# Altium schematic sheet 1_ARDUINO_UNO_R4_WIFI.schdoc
size 601 x 429 mm; Symbol: Drawing-Symbol_A4; Device: Drawing-Symbol_A4; @Project Name: Slowpoke; @Page Count: 1; @Update Date: 2025-12-13; @Create Date: 2025-12-13; @Schematic Name: Schematic2; @Page No: 1; @Page Name: ARDUINO_UNO_R4_WIFI; Company: EasyEDA.com; Version: V1.0; Page Size: A4; @Create Time: 06:28:29; @Update Time: 14:28:55; Width: 2338; Height: 1652; Region Start: 1; X Region Count: 6; Y Region Count: 4; Blade Width: 10; Title Block Position: 3; @Board Name: ARDUINO
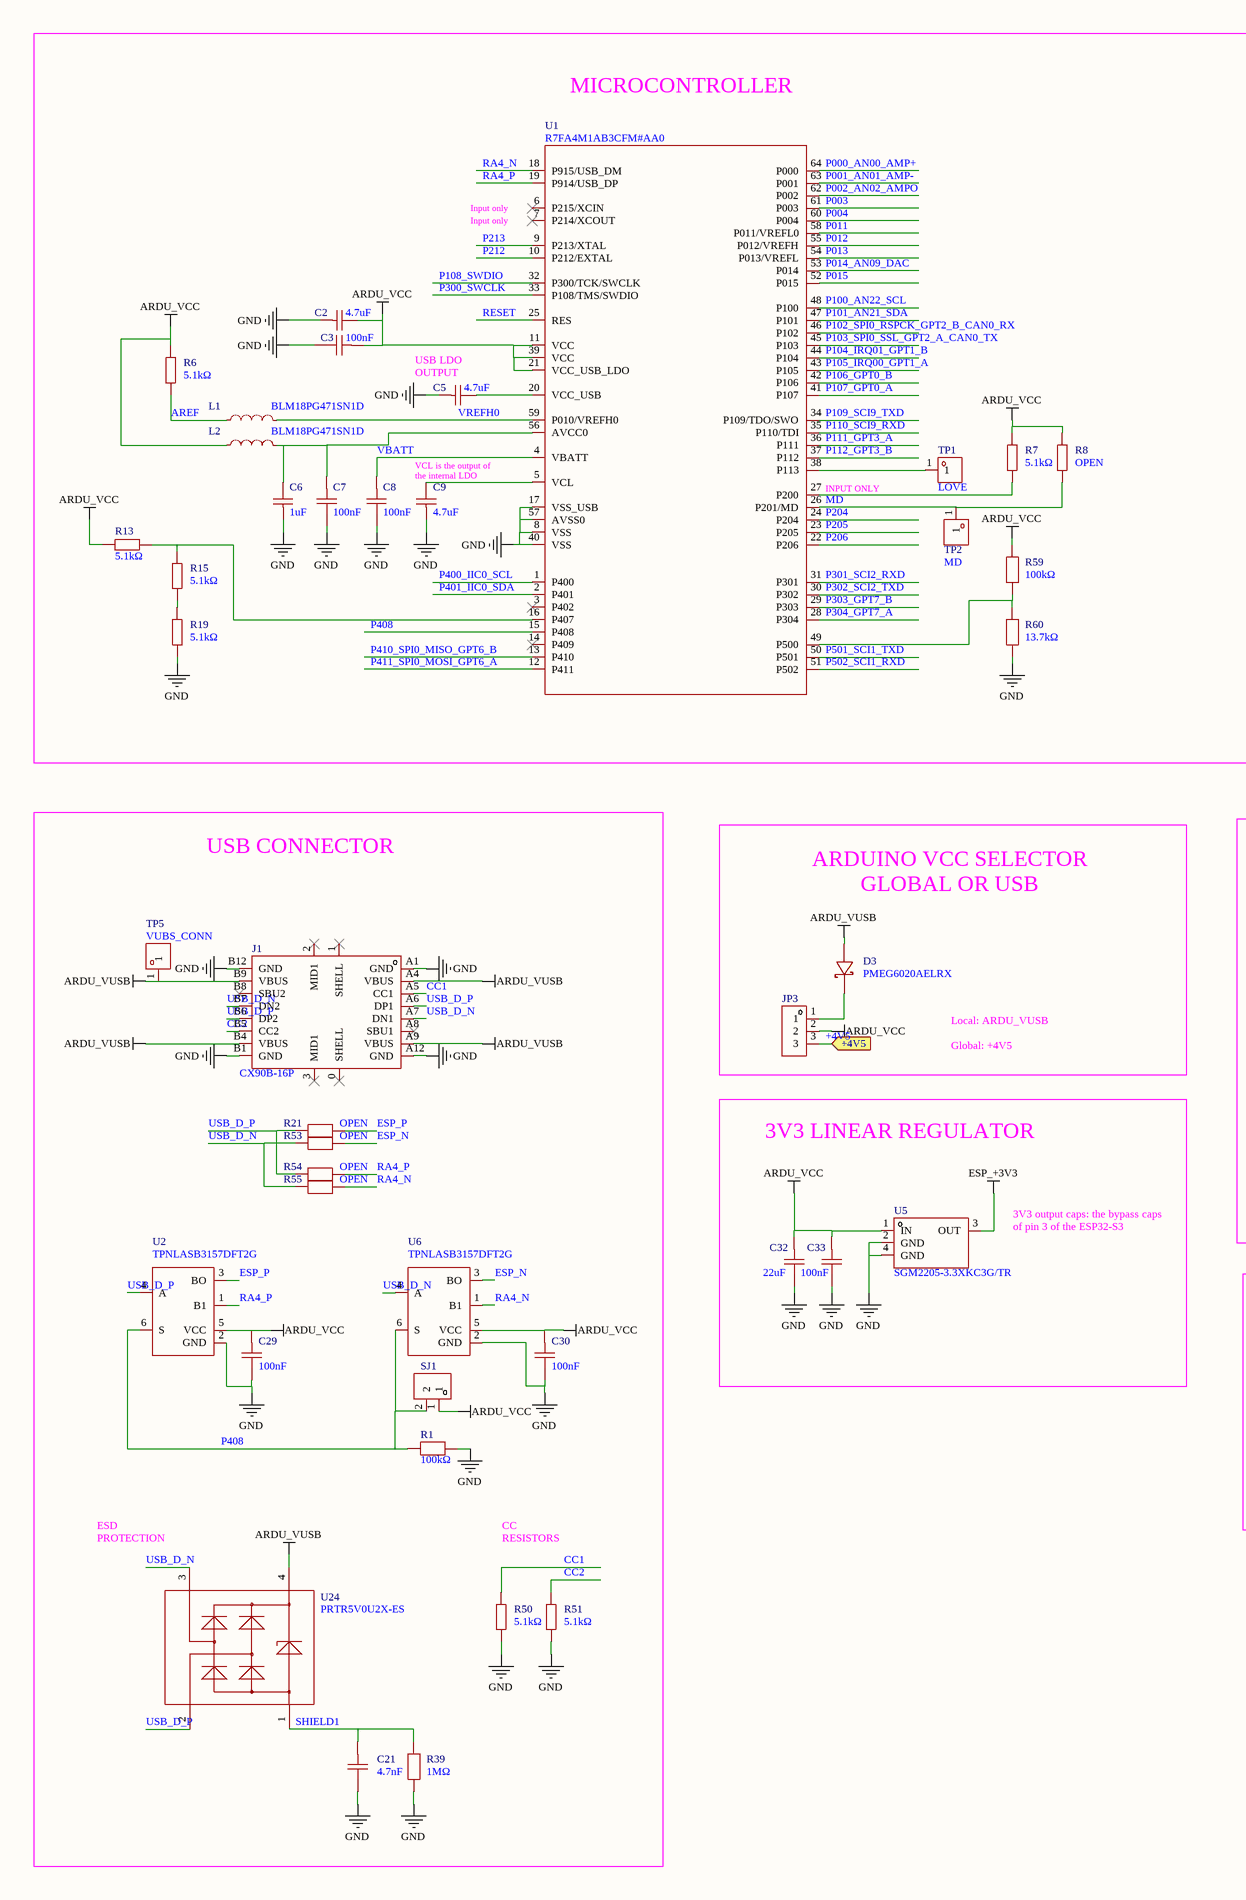
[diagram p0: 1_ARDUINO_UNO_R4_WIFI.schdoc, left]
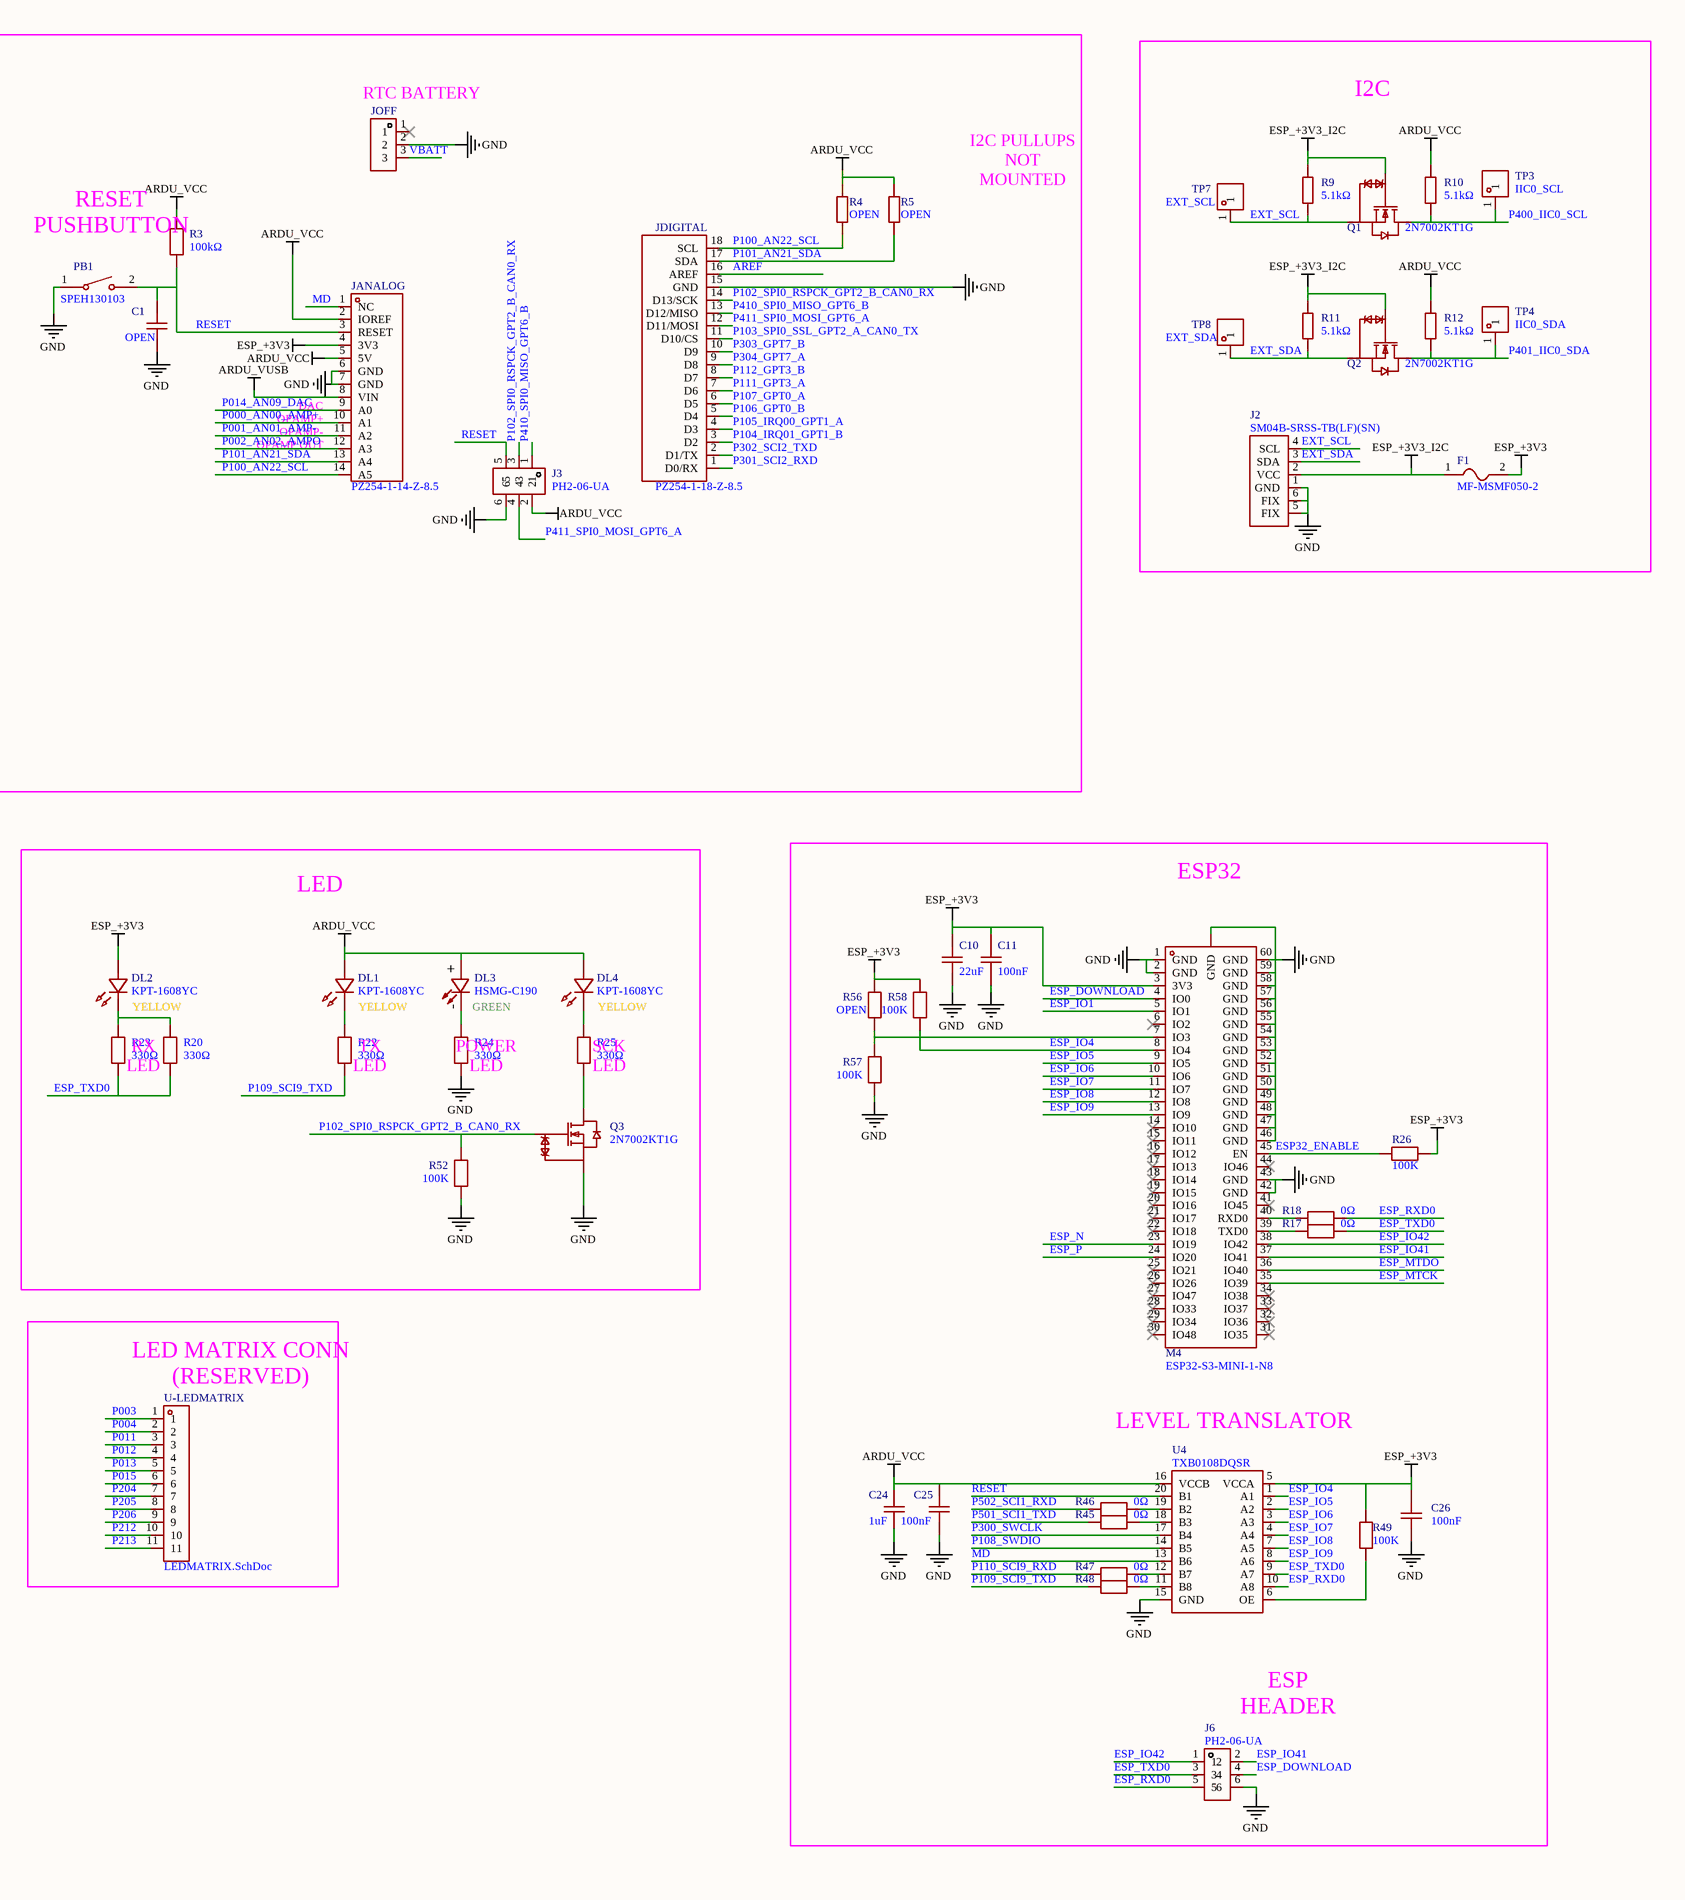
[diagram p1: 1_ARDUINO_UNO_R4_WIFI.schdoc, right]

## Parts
C1  OPEN  [C0402]
C2  4.7uF  [C0402]
C3  100nF  [C0402]
C5  4.7uF  [C0402]
C6  1uF  [C0402]
C7  100nF  [C0402]
C8  100nF  [C0402]
C9  4.7uF  [C0402]
C10  22uF  [C0805]
C11  100nF  [C0402]
C21  4.7nF  [C0805]
C24  1uF  [C0402]
C25  100nF  [C0402]
C26  100nF  [C0402]
C29  100nF  [C0402]
C30  100nF  [C0402]
C32  22uF  [C0805]
C33  100nF  [C0402]
D3  PMEG6020AELRX  [SOD-123_L2.6-W1.7-LS3.5-RD]
DL1  KPT-1608YC  [LED-SMD_L1.6-W0.8-RD]
DL2  KPT-1608YC  [LED-SMD_L1.6-W0.8-RD]
DL3  HSMG-C190  [LED-SMD_L1.6-W0.8-R-RD]
DL4  KPT-1608YC  [LED-SMD_L1.6-W0.8-RD]
F1  MF-MSMF050-2  [F1812]
J1  CX90B-16P  [USB-C-SMD_CX90B-16P]
J2  SM04B-SRSS-TB(LF)(SN)  [CONN-SMD_4P-P1.00_SM04B-SRSS-TB-LF-SN]
J3  PH2-06-UA  [HDR-TH_6P-P2.54-V-M-R2-C3-S2.54-1]
J6  PH2-06-UA  [HDR-TH_6P-P2.54-V-M-R2-C3-S2.54-1]
JANALOG  PZ254-1-14-Z-8.5  [HDR-TH_14P-P2.54-V-M]
JDIGITAL  PZ254-1-18-Z-8.5  [HDR-TH_18P-P2.54-V-M]
JOFF  PZ254V-11-03P  [HDR-TH_3P-P2.54-V-M]  (value not drawn)
JP3  PZ254V-11-03P  [HDR-TH_3P-P2.54-V-M]  (value not drawn)
L1  BLM18PG471SN1D  [L0603]
L2  BLM18PG471SN1D  [L0603]
M4  ESP32-S3-MINI-1-N8  [BULETM-SMD_ESP32-S3-MINI-1-N8]
PB1  SPEH130103  [SW-SMD_L6.0-W6.0-LS6.6]
Q1  2N7002KT1G  [SOT-23-3_L2.9-W1.3-P1.90-LS2.4-BR]
Q2  2N7002KT1G  [SOT-23-3_L2.9-W1.3-P1.90-LS2.4-BR]
Q3  2N7002KT1G  [SOT-23-3_L2.9-W1.3-P1.90-LS2.4-BR]
R1  100kΩ  [R0402]
R3  100kΩ  [R0402]
R4  OPEN  [R0402]
R5  OPEN  [R0402]
R6  5.1kΩ  [R0402]
R7  5.1kΩ  [R0402]
R8  OPEN  [R0402]
R9  5.1kΩ  [R0402]
R10  5.1kΩ  [R0402]
R11  5.1kΩ  [R0402]
R12  5.1kΩ  [R0402]
R13  5.1kΩ  [R0402]
R15  5.1kΩ  [R0402]
R17  0Ω  [R0402]
R18  0Ω  [R0402]
R19  5.1kΩ  [R0402]
R20  330Ω  [R0402]
R21  OPEN  [R0402]
R22  330Ω  [R0402]
R23  330Ω  [R0402]
R24  330Ω  [R0402]
R25  330Ω  [R0402]
R26  100K  [R0402]
R39  1MΩ  [R0402]
R45  0Ω  [R0402]
R46  0Ω  [R0402]
R47  0Ω  [R0402]
R48  0Ω  [R0402]
R49  100K  [R0402]
R50  5.1kΩ  [R0402]
R51  5.1kΩ  [R0402]
R52  100K  [R0402]
R53  OPEN  [R0402]
R54  OPEN  [R0402]
R55  OPEN  [R0402]
R56  OPEN  [R0402]
R57  100K  [R0402]
R58  100K  [R0402]
R59  100kΩ  [R0402]
R60  13.7kΩ  [R0402]
SJ1  IOVDD_1797  [HDR-TH_2P-P2.54-V-M]  (value not drawn)
TP1  LOVE  [TESTPOINT-TH_BD3.2]
TP2  MD  [TESTPOINT-TH_BD3.2]
TP3  IIC0_SCL  [TESTPOINT-TH_BD3.2]
TP4  IIC0_SDA  [TESTPOINT-TH_BD3.2]
TP5  VUBS_CONN  [TESTPOINT-TH_BD3.2]
TP7  EXT_SCL  [TESTPOINT-TH_BD3.2]
TP8  EXT_SDA  [TESTPOINT-TH_BD3.2]
U1  R7FA4M1AB3CFM#AA0  [LQFP-64_L10.0-W10.0-P0.50-LS12.0-BL]
U2  TPNLASB3157DFT2G  [SOT-363-6_L2.0-W1.3-P0.65-LS2.3-BL]
U4  TXB0108DQSR  [SON-20_L4.0-W2.0-P0.40-BL]
U5  SGM2205-3.3XKC3G/TR  [SOT-223-3_L6.5-W3.4-P2.30-LS7.0-BR]
U6  TPNLASB3157DFT2G  [SOT-363-6_L2.0-W1.3-P0.65-LS2.3-BL]
U24  PRTR5V0U2X-ES  [SOT-143_L2.9-W1.3-P1.92-LS2.3-BR]
U-LEDMATRIX  LEDMATRIX.SchDoc  [HDR-TH_11P-P2.54-V-M]

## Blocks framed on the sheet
MICROCONTROLLER: C1-C3 C5-C9 J3 JANALOG JDIGITAL JOFF L1 L2 PB1 R3-R8 R13 R15 R19 R59 R60 TP1 TP2 U1
I2C: F1 J2 Q1 Q2 R9-R12 TP3 TP4 TP7 TP8
USB CONNECTOR: C21 C29 C30 J1 R1 R21 R39 R50 R51 R53-R55 SJ1 TP5 U2 U6 U24
LED: DL1-DL4 Q3 R20 R22-R25 R52
3V3 LINEAR REGULATOR: C32 C33 U5

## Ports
+4V5 (in)

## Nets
ARDU_VCC: C2.2 C3.2 C24.2 C25.2 C29.2 C30.2 C32.2 C33.2 DL1.2(A) DL3.1(A) DL4.2(A) J3.2 JANALOG.2(IOREF) JANALOG.5(5V) JP3.2 L2.1 R3.2 R4.2 R5.2 R6.2 R7.2 R8.2 R10.2 R12.2 R13.2 R59.2 SJ1.1 U1.11(VCC) U1.21(VCC_USB_LDO) U1.39(VCC) U2.5(VCC) U4.16(VCCB) U5.1(IN) U6.5(VCC)
ARDU_VUSB: D3.2(+) J1.A4(VBUS) J1.A9(VBUS) J1.B4(VBUS) J1.B9(VBUS) JANALOG.8(VIN) TP5.1 U24.4(VCC)
ESP_+3V3: C10.2 C11.2 C26.2 DL2.2(A) F1.2 JANALOG.4(3V3) M4.3(3V3) R26.1 R49.2 R56.2 R58.2 U4.5(VCCA) U5.3(OUT)
ESP_+3V3_I2C: F1.1 J2.2(VCC) Q1.1(G) Q2.1(G) R9.2 R11.2
GND: C1.1 C2.1 C3.1 C5.1 C6.1 C7.1 C8.1 C9.1 C10.1 C11.1 C21.1 C24.1 C25.1 C26.1 C29.1 C30.1 C32.1 C33.1 J1.A1(GND) J1.A12(GND) J1.B1(GND) J1.B12(GND) J2.1(GND) J2.5(FIX) J2.6(FIX) J3.6 J6.6 JANALOG.6(GND) JANALOG.7(GND) JDIGITAL.15(GND) JOFF.2 M4.1(GND) M4.2(GND) M4.42(GND) M4.43(GND) M4.46(GND) M4.47(GND) M4.48(GND) M4.49(GND) M4.50(GND) M4.51(GND) M4.52(GND) M4.53(GND) M4.54(GND) M4.55(GND) M4.56(GND) M4.57(GND) M4.58(GND) M4.59(GND) M4.60(GND) M4.GND PB1.1 Q3.2(S) R1.1 R19.1 R24.1 R39.1 R50.1 R51.1 R52.1 R57.1 R60.1 U1.8(VSS) U1.17(VSS_USB) U1.40(VSS) U1.57(AVSS0) U2.2(GND) U4.15(GND) U5.2(GND) U5.4(GND) U6.2(GND)
+4V5: JP3.3 ; port +4V5
AREF: JDIGITAL.16(AREF) L1.1 R6.1
CC1: J1.A5(CC1) R50.2
CC2: J1.B5(CC2) R51.2
ESP32_ENABLE: M4.45(EN) R26.2
ESP_DOWNLOAD: J6.4 M4.4(IO0)
ESP_IO1: M4.5(IO1)
ESP_IO4: M4.8(IO4) R58.1 U4.1(A1)
ESP_IO5: M4.9(IO5) U4.2(A2)
ESP_IO6: M4.10(IO6) U4.3(A3)
ESP_IO7: M4.11(IO7) U4.4(A4)
ESP_IO8: M4.12(IO8) U4.7(A5)
ESP_IO9: M4.13(IO9) U4.8(A6)
ESP_IO41: J6.2 M4.37(IO41)
ESP_IO42: J6.1 M4.38(IO42)
ESP_MTCK: M4.35(IO39)
ESP_MTDO: M4.36(IO40)
ESP_N: M4.23(IO19) R53.2 U6.3(BO)
ESP_P: M4.24(IO20) R21.2 U2.3(BO)
ESP_RXD0: J6.5 R18.2 U4.10(A8)
ESP_TXD0: J6.3 R17.2 R20.1 R23.1 U4.9(A7)
EXT_SCL: J2.4(SCL) Q1.2(S) R9.1 TP7.1
EXT_SDA: J2.3(SDA) Q2.2(S) R11.1 TP8.1
MD: JANALOG.1(NC) R8.1 TP2.1 U1.26(P201/MD) U4.13(B6)
P000_AN00_AMP+: JANALOG.10(A1) U1.64(P000)
P001_AN01_AMP-: JANALOG.11(A2) U1.63(P001)
P002_AN02_AMPO: JANALOG.12(A3) U1.62(P002)
P003: U1.61(P003) U-LEDMATRIX.1
P004: U1.60(P004) U-LEDMATRIX.2
P011: U1.58(P011/VREFL0) U-LEDMATRIX.3
P012: U1.55(P012/VREFH) U-LEDMATRIX.4
P013: U1.54(P013/VREFL) U-LEDMATRIX.5
P014_AN09_DAC: JANALOG.9(A0) U1.53(P014)
P015: U1.52(P015) U-LEDMATRIX.6
P100_AN22_SCL: JANALOG.14(A5) JDIGITAL.18(SCL) R4.1 U1.48(P100)
P101_AN21_SDA: JANALOG.13(A4) JDIGITAL.17(SDA) R5.1 U1.47(P101)
P102_SPI0_RSPCK_GPT2_B_CAN0_RX: J3.3 JDIGITAL.14(D13/SCK) Q3.1(G) R52.2 U1.46(P102)
P103_SPI0_SSL_GPT2_A_CAN0_TX: JDIGITAL.11(D10/CS) U1.45(P103)
P104_IRQ01_GPT1_B: JDIGITAL.3(D2) U1.44(P104)
P105_IRQ00_GPT1_A: JDIGITAL.4(D3) U1.43(P105)
P106_GPT0_B: JDIGITAL.5(D4) U1.42(P106)
P107_GPT0_A: JDIGITAL.6(D5) U1.41(P107)
P108_SWDIO: U1.32(P300/TCK/SWCLK) U4.14(B5)
P109_SCI9_TXD: R22.1 R48.1 U1.34(P109/TDO/SWO)
P110_SCI9_RXD: R47.1 U1.35(P110/TDI)
P111_GPT3_A: JDIGITAL.7(D6) U1.36(P111)
P112_GPT3_B: JDIGITAL.8(D7) U1.37(P112)
P204: U1.24(P204) U-LEDMATRIX.7
P205: U1.23(P205) U-LEDMATRIX.8
P206: U1.22(P206) U-LEDMATRIX.9
P212: U1.10(P212/EXTAL) U-LEDMATRIX.10
P213: U1.9(P213/XTAL) U-LEDMATRIX.11
P300_SWCLK: U1.33(P108/TMS/SWDIO) U4.17(B4)
P301_SCI2_RXD: JDIGITAL.1(D0/RX) U1.31(P301)
P302_SCI2_TXD: JDIGITAL.2(D1/TX) U1.30(P302)
P303_GPT7_B: JDIGITAL.10(D9) U1.29(P303)
P304_GPT7_A: JDIGITAL.9(D8) U1.28(P304)
P400_IIC0_SCL: Q1.3(D) R10.1 TP3.1 U1.1(P400)
P401_IIC0_SDA: Q2.3(D) R12.1 TP4.1 U1.2(P401)
P408: R1.2 SJ1.2 U1.15(P408) U2.6(S) U6.6(S)
P410_SPI0_MISO_GPT6_B: J3.1 JDIGITAL.13(D12/MISO) U1.13(P410)
P411_SPI0_MOSI_GPT6_A: J3.4 JDIGITAL.12(D11/MOSI) U1.12(P411)
P501_SCI1_TXD: R45.1 U1.50(P501)
P502_SCI1_RXD: R46.1 U1.51(P502)
RA4_N: R55.2 U1.18(P915/USB_DM) U6.1(B1)
RA4_P: R54.2 U1.19(P914/USB_DP) U2.1(B1)
RESET: C1.2 J3.5 JANALOG.3(RESET) PB1.2 R3.1 U1.25(RES) U4.20(B1)
SHIELD1: C21.2 R39.2 U24.1(GND)
USB_D_N: J1.A7(DN1) J1.B7(DN2) R53.1 R55.1 U6.4(A) U24.3(IO)
USB_D_P: J1.A6(DP1) J1.B6(DP2) R21.1 R54.1 U2.4(A) U24.2(IO)
VBATT: C8.2 JOFF.3 U1.4(VBATT)
VREFH0: L1.2 U1.59(P010/VREFH0)
NetC5_2: C5.2 U1.20(VCC_USB)
NetC6_2: C6.2 C7.2 L2.2 U1.56(AVCC0)
NetC9_2: C9.2 U1.5(VCL)
NetD3_1: D3.1(-) JP3.1
NetDL1_1: DL1.1(K) R22.2
NetDL2_1: DL2.1(K) R20.2 R23.2
NetDL3_2: DL3.2(C) R24.2
NetDL4_1: DL4.1(K) R25.2
NetM4_7: M4.7(IO3) R56.1 R57.2
NetM4_39: M4.39(TXD0) R17.1
NetM4_40: M4.40(RXD0) R18.1
NetQ3_3: Q3.3(D) R25.1
NetR7_1: R7.1 U1.27(P200)
NetR13_1: R13.1 R15.2 U1.16(P407)
NetR15_1: R15.1 R19.2
NetR45_2: R45.2 U4.18(B3)
NetR46_2: R46.2 U4.19(B2)
NetR47_2: R47.2 U4.12(B7)
NetR48_2: R48.2 U4.11(B8)
NetR49_1: R49.1 U4.6(OE)
NetR59_1: R59.1 R60.2 U1.49(P500)
NetTP1_1: TP1.1 U1.38(P113)

Not connected (* = marked no-connect by the designer): J1 0(SHELL)* 1(SHELL)* 2(MID1)* 3(MID1)* A8(SBU1)* B8(SBU2)*; JOFF 1*; M4 6(IO2)* 14(IO10)* 15(IO11)* 16(IO12)* 17(IO13)* 18(IO14)* 19(IO15)* 20(IO16)* 21(IO17)* 22(IO18)* 25(IO21)* 26(IO26)* 27(IO47)* 28(IO33)* 29(IO34)* 30(IO48)* 31(IO35)* 32(IO36)* 33(IO37)* 34(IO38)* 41(IO45)* 44(IO46)*; U1 3(P402)* 6(P215/XCIN)* 7(P214/XCOUT)* 14(P409)*

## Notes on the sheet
- (near JOFF) RTC BATTERY
- RESET
  PUSHBUTTON
- I2C PULLUPS
  NOT
  MOUNTED
- (near U1) Input only
- (near C5) USB LDO
  OUTPUT
- (near JANALOG) DAC
  OPAMP+
  OPAMP-
  OPAMP OUT
- (near C9) VCL is the output of
  the internal LDO
- (near U1) INPUT ONLY
- (near D3) ARDUINO VCC SELECTOR
  GLOBAL OR USB
- ESP32
- YELLOW
- GREEN
- Local: ARDU_VUSB
  Global: +4V5
- RX
  LED
- (near R22) TX
  LED
- POWER
  LED
- SCK
  LED
- (near U5) 3V3 output caps: the bypass caps
  of pin 3 of the ESP32-S3
- (near U-LEDMATRIX) LED MATRIX CONN
  (RESERVED)
- LEVEL TRANSLATOR
- (near U24) ESD
  PROTECTION
- CC
  RESISTORS
- (near J6) ESP
  HEADER

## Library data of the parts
C1 = CC0402KRX7R6BB474: Manufacturer: YAGEO(国巨); Add into BOM: yes; Tolerance: ±10%; Voltage Rating: 10V; Temperature Coefficient: X7R
C2 C5 C6 C9 C24 = CL05A105KP5NNNC: Manufacturer: SAMSUNG(三星); Add into BOM: yes; Tolerance: ±10%; Voltage Rating: 10V; Temperature Coefficient: X5R
C3 C7 C8 C11 C25 C26 C29 C30 C33 = GRM155R61H104KE19D: Manufacturer: muRata(村田); Add into BOM: yes; Tolerance: ±10%
C10 C32 = CL21A226MAQNNNE: Manufacturer: SAMSUNG(三星); Add into BOM: yes; Tolerance: ±20%; Voltage Rating: 25V; Temperature Coefficient: X5R
C21 = FV21X472K102ECG: Manufacturer: PSA(信昌电陶); Add into BOM: yes; Tolerance: ±10%; Voltage Rating: 1kV; Temperature Coefficient: X7R
D3 = PMEG6020AELRX: Manufacturer: Nexperia(安世); Add into BOM: yes; Forward Voltage (Vf@If): 670mV@2A; Reverse Voltage (Vr): 60V; Average Rectified Current (Io): 2A; Reverse Leakage Current (Ir): 700nA@60V
DL1 DL2 DL4 = VFHL1116P-4BX3C-TR: Manufacturer: Stanley Electric; Add into BOM: yes; Illumination Color: Emerald; Voltage - Forward(Vf): 1.9V; Forward Current: 20mA; Wavelength - Dominant: 562nm; Peak Wavelength: 565nm; Lens Color: White Lens; Luminous Intensity: 82mcd
DL3 = HSMG-C190: Manufacturer: Broadcom(博通); Add into BOM: yes; Illumination Color: Green; Voltage - Forward(Vf): 2.2V; Power(Watts): 52mW; Forward Current: 20mA; Wavelength - Dominant: 572nm; Peak Wavelength: 570nm; Luminous Intensity: 15mcd; Viewing Angle: 170°
F1 = MF-MSMF050-2: Manufacturer: BOURNS; Add into BOM: yes; Voltage - Max: 15V; Current - Max: 100A; Hold Current: 500mA; Trip Current: 1A; Resistance - Initial (Ri) (Min): 150mΩ; Resistance - Post Trip (R1) (Max): 1Ω; Time to Trip(Max): 150ms
J1 = CX90B-16P: Manufacturer: HRS(广濑); Add into BOM: yes
J2 = SM04B-SRSS-TB(LF)(SN): Manufacturer: JST; Add into BOM: yes; Pins Structure: 1x4P; Pitch: 1mm; Reference Series: SH; Number of PINs Per Row: 4; Current Rating: 1A; Voltage Rating: 50V; Plastic Material: PA; Flame Retardant Rating: UL94V-0; Supplementary Features: Auxiliary Solder Pin; Z-Height of the Board: 2.9mm; X-Length of Bottom Edge on Board (Spacing Line): 6mm; Y-Width of Bottom Edge on Board: 4.32mm
J3 J6 = PH2-06-UA: Manufacturer: ADAM TECH; Add into BOM: yes; Pitch: 2.54mm; Circluar Pins/Square Pins: Pin Header; Current Rating: 3A; Voltage Rating (Max): 250V
JANALOG = PZ254-1-14-Z-8.5: Manufacturer: HCTL(华灿天禄); Symbol: PM254-1-14-Z-8.5; Add into BOM: yes; Pin Structure: 1x14P; Pitch: 2.54mm; Circluar Pins/Square Pins: Policy; Current Rating: 3A
JDIGITAL = PZ254-1-18-Z-8.5: Manufacturer: HCTL(华灿天禄); Symbol: PM254-1-18-Z-8.5; Add into BOM: yes; Pin Structure: 1x18P; Pitch: 2.54mm; Circluar Pins/Square Pins: Pin Header; Current Rating: 3A
JOFF JP3 = PZ254V-11-03P: Manufacturer: XFCN(兴飞); Symbol: PZ254V-11-03P_C2937625; Add into BOM: yes; Pin Structure: 1x3P; Pitch: 2.54mm; Circluar Pins/Square Pins: Pin Header; Current Rating: 3A; Voltage Rating (Max): 250V
L1 L2 = BLM18PG471SN1D: Manufacturer: muRata(村田); Add into BOM: yes; Impedance @ Frequency: 470Ω@100MHz; Tolerance: ±25%; DC Resistance(DCR): 200mΩ; Current Rating: 1A; Number of Circuits: 1
M4 = ESP32-S3-MINI-1-N8: Manufacturer: ESPRESSIF(乐鑫); Add into BOM: yes; Core Processor: ESP32-S3FN8 Chip; Support Interface: I2C；GPIO；SPI；PWM；ADC；UART；USB；I2S; Output Power: 20.5dBm
PB1 = SPEH130103: Manufacturer: ALPSALPINE(阿尔卑斯阿尔派); Add into BOM: yes; Actuator Style: Square Button; Contact Current: 50mA; Voltage Rating: 16V; Actuator/Cap Color: Black; Operating Force: 3N
Q1-Q3 = 2N7002KT1G: Manufacturer: onsemi(安森美); Add into BOM: yes; Number: 1 N-Channel; Drain to Source Voltage: 60V; Current - Continuous Drain(Id): 380mA; RDS(on): 2.5Ω@4.5V,200mA; Pd - Power Dissipation: 420mW; Gate Threshold Voltage (Vgs(th)): 2.3V@250uA; Gate Charge(Qg): 700pC@4.5V; Input Capacitance(Ciss): 45pF; Type: N-Channel
R1 R3 = CRCW0402100KFKEDC: Manufacturer: VISHAY(威世); Add into BOM: yes; Tolerance: ±1%; Power(Watts): 62.5mW; Temperature Coefficient: ±100ppm/℃
R4-R13 R15 R19 R50 R51 = RC0402FR-075K1L: Manufacturer: YAGEO(国巨); Add into BOM: yes; Tolerance: ±1%; Power(Watts): 62.5mW; Voltage-Supply(Max): 50V; Temperature Coefficient: ±100ppm/℃
R17 R18 R21 R45-R48 R53-R55 = CRCW04020000Z0EDC: Manufacturer: VISHAY(威世); Add into BOM: yes; Power(Watts): 62.5mW; Voltage-Supply(Max): 50V
R20 R22-R25 = CRCW0402330RJNED: Manufacturer: VISHAY(威世); Add into BOM: yes; Tolerance: ±5%; Power(Watts): 62.5mW; Voltage-Supply(Max): 50V; Temperature Coefficient: ±200ppm/℃
R26 R49 R52 R56-R59 = ERA2AEB104X: Manufacturer: PANASONIC(松下); Add into BOM: yes; Tolerance: ±0.1%; Power(Watts): 63mW; Voltage-Supply(Max): 50V; Temperature Coefficient: ±25ppm/℃
R39 = CRCW04021M00FKED: Manufacturer: VISHAY(威世); Add into BOM: yes; Tolerance: ±1%; Power(Watts): 63mW; Voltage-Supply(Max): 50V; Temperature Coefficient: ±100ppm/℃
R60 = RT0402BRD0713K7L: Manufacturer: YAGEO(国巨); Add into BOM: yes; Tolerance: ±0.1%; Temperature Coefficient: ±25ppm/℃
SJ1 = PZ254V-11-02P: Manufacturer: XFCN(兴飞); Add into BOM: yes; Pin Structure: 1x2P; Pitch: 2.54mm; Circluar Pins/Square Pins: Pin Header
TP1-TP5 TP7 TP8 = RH-5011: Manufacturer: 荣和; Add into BOM: yes; Connector Type: Pin type (through board); Plastic Color: Black
U1 = R7FA4M1AB3CFM#AA0: Manufacturer: RENESAS(瑞萨)/IDT; Add into BOM: yes; CPU Core: ARM-M4; CPU Maximum Speed: 48MHz; Program Storage Size: 256KB; Program Memory Type: FLASH; Number of I/O: 52; ADC (Bit): 14bit; DAC (Bit): 12bit；8bit; Voltage - Supply: 1.6V~5.5V
U2 U6 = TPNLASB3157DFT2G: Manufacturer: TECH PUBLIC(台舟); Add into BOM: yes
U4 = TXB0108DQSR: Manufacturer: TI(德州仪器); Add into BOM: yes
U5 = SGM2205-3.3XKC3G/TR: Manufacturer: SGMICRO(圣邦微); Add into BOM: yes; Output Type: Fixed; Voltage - Supply: 20V; Output Voltage: 3.3V; Output Current: 800mA; Power Supply Rejection Ratio (PSRR): 75dB@(1kHz); Voltage Dropout: 850mV@(800mA); standby current: 112uA; Output Configuration: Positive; Number of Outputs: 1
U24 = PRTR5V0U2X-ES: Manufacturer: ElecSuper(静芯); Add into BOM: yes; Polarity: Unidirectional; Reverse Stand-Off Voltage (Vrwm): 5V; Clamping Voltage: 18V; Peak Pulse Current (Ipp): 9A@8/20us; Peak Pulse Power Dissipation (Ppp): 180W@8/20us; Voltage - Breakdown: 6V; Reverse Leakage Current (Ir): 1uA; Number of Channels: 2; level of protection: IEC 61000-4-2；IEC 61000-4-4；IEC 61000-4-5; Junction Capacitance: 0.8pF；1.6pF
U-LEDMATRIX = HB-PH3-254111PB2GOP: Manufacturer: HANBO(汉博); Add into BOM: yes; Pin Structure: 1x11P; Pitch: 2.54mm; Circluar Pins/Square Pins: Pin Header; Current Rating: 3A; Voltage Rating (Max): 250V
